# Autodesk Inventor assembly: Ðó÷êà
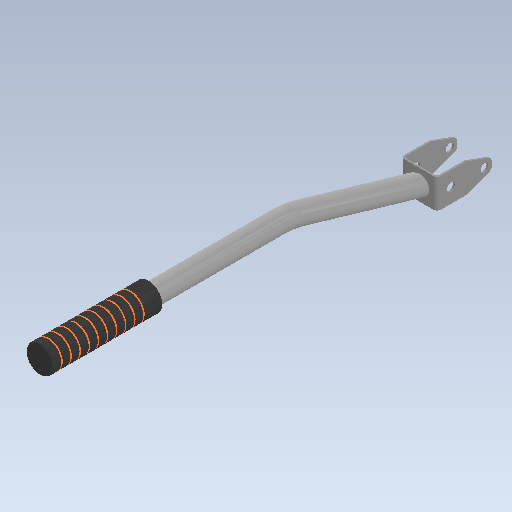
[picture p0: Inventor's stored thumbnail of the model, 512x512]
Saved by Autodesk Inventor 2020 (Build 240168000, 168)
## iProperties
Created: 1900-01
Part Number: Ðó÷êà
Document SubType Name: Assembly
Designer: bruno
Author: bruno
Revision Number: ANYUNSPECIFIED
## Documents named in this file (4)
- C:\Users\bruno\Documents\1-Cours-2022-23\1SI\2. Cinématique\Hoverboard\Inventor-Hoverboard\Poignee-1.iam
- C:\Users\bruno\Downloads\Òðóáà ðó÷êè.ipt
- C:\Users\bruno\Downloads\Âèëêà ðó÷êè.ipt
- C:\Users\bruno\Documents\1-Cours-2022-23\1SI\2. Cinématique\Hoverboard\Inventor-Hoverboard\HANDLE GRIP_1.ipt
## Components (3 placed, 3 different names)
1. 25
2. 26
3. 27
